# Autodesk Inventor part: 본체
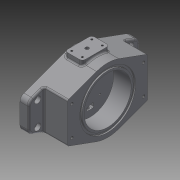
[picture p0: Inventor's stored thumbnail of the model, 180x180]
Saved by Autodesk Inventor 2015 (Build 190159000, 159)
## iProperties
Created: 2023-11
Part Number: 본체
Material: 알루미늄 6061
Document SubType Name: Modeling
Designer: user
Density: 2.7 g/cm^3
Appearance: 기본값
Mass: 1561.22 g
Surface Area: 721.057 cm^2
Volume: 578.228 cm^3
Author: user
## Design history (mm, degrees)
sketch "스케치2"
  geometry: L1 (18.811, 51.683)-(94, 24.317); L2 (94, 24.317)-(94, -24.317); L3 (18.811, -51.683)-(94, -24.317); L4 (0, 0)-(66.664, 0); L5 (0, 55)-(0, -55); L6 (-18.811, 51.683)-(-94, 24.317); L7 (-94, 24.317)-(-94, -24.317); L8 (-18.811, -51.683)-(-94, -24.317); A1 r 55 centre (0, 0) between (18.811, 51.683) and (-18.811, 51.683); A2 r 55 centre (0, 0) between (-18.811, -51.683) and (18.811, -51.683); 1 further point
  constraints: 16 end point, 6 point on circle, 4 symmetric about line, 2 centre point, 2 tangent, 2 vertical, 1 coincident, 1 horizontal, 1 other
  dimensions: "d3" = 94 distance from line of point (0, 0) L2; "d4" = 40 deg angle of L1 L3; "d5" = 55 radius of A1
extrude "돌출1" new body sketch "스케치2" distance "d6" = 15; taper "d7" = 0 deg
sketch "스케치4"
  geometry: L1 (-24.317, 94)-(-51.683, 18.811) reference; L2 (-51.683, -18.811)-(-24.317, -94) reference; L3 (-24.317, -94)-(24.317, -94) reference; L4 (51.683, 18.811)-(24.317, 94) reference; L5 (24.317, 94)-(-24.317, 94) reference; L6 (51.683, -18.811)-(24.317, -94) reference; L7 (-33.78, 68)-(33.78, 68); L8 (-33.78, 68)-(-51.683, 18.811); L9 (33.78, 68)-(51.683, 18.811); L10 (-33.78, -68)-(33.78, -68); L11 (-33.78, -68)-(-51.683, -18.811); L12 (-24.317, -94)-(-51.683, -18.811) reference; L13 (33.78, -68)-(51.683, -18.811); A1 r 55 centre (0, 0) between (-51.683, 18.811) and (-51.683, -18.811) reference; A2 r 55 centre (0, 0) between (51.683, -18.811) and (51.683, 18.811) reference; A3 r 55 centre (0, 0) between (-51.683, 18.811) and (-51.683, -18.811); A4 r 55 centre (0, 0) between (51.683, -18.811) and (51.683, 18.811)
  constraints: 13 end point, 4 point on circle, 4 point on line, 2 centre point, 2 horizontal, 2 parallel, 1 coincident, 1 collinear
  dimensions: "d13" = 68 distance from line of A1.centre L7; "d14" = 68 distance from line of A1.centre L10
extrude "돌출3" join sketch "스케치4" distance "d15" = 40; taper "d16" = 0 deg
sketch "스케치5"
  geometry: C1 r 40 at (0, 0); A1 r 55 centre (0, 0) between (51.683, -18.811) and (51.683, 18.811) reference
  constraints: 1 centre point, 1 coincident
  dimensions: "d17" = 80 diameter of C1
extrude "돌출4" cut sketch "스케치5" distance "d18" = 30; taper "d19" = 0 deg
node "작업 평면1"
sketch "스케치8"
  geometry: L1 (0, 18.811)-(0, -18.811) reference; L2 (10, -23)-(30, -23); L3 (35, -18)-(35, 18); L4 (30, 23)-(10, 23); L5 (5, 18)-(5, -18); L6 (5, -23)-(35, 23); L7 (35, -23)-(5, 23); L8 (0, 18.811)-(0, 94) reference; A1 r 5 centre (10, 18) between (10, 23) and (5, 18); A2 r 5 centre (30, 18) between (35, 18) and (30, 23); A3 r 5 centre (30, -18) between (30, -23) and (35, -18); A4 r 5 centre (10, -18) between (5, -18) and (10, -23); 4 further points
  constraints: 12 end point, 8 point on circle, 8 point on line, 8 tangent, 4 centre point, 4 midpoint, 3 equal radius, 2 parallel, 1 horizontal, 1 horizontal alignment, 1 perpendicular
  dimensions: "d31" = 30 distance of L6.end L7.end; "d32" = 46 distance of L7.end L6.start; "d33" = 20 distance from line of L8 point (20, 0); "d49" = 5 radius of A1
extrude "돌출6" join sketch "스케치8" stored distance "d34" = 20; taper "d35" = 0 deg
sketch "스케치9"
  geometry: C1 r 47.5 at (0, 0); C2 r 43.4 at (0, 0); A1 r 55 centre (0, 0) between (51.683, -18.811) and (51.683, 18.811) reference
  constraints: 2 centre point, 2 coincident
  dimensions: "d36" = 95 diameter of C1; "d37" = 4.1 radial gap between concentric circles of C1 C2
extrude "돌출7" cut sketch "스케치9" distance "d38" = 2.4; taper "d39" = 0 deg
sketch "스케치10"
  geometry: L1 (33.78, 68)-(-33.78, 68) reference; L2 (24.317, -94)-(-24.317, -94) reference; L3 (0, 0)-(0, 111.421); L4 (0, 0)-(71.748, 0); 4 further points
  constraints: 4 end point, 2 horizontal alignment, 2 symmetric about line, 2 vertical alignment, 1 horizontal, 1 vertical
  dimensions: "d40" = 158 distance of point (-20, -79) point (-20, 79); "d41" = 40 distance of point (20, -79) point (-20, -79)
hole "구멍2" sketch "스케치10" at (-20, 79), (20, 79), (-20, -79), (20, -79) diameter "d42" = 6.6; stored, may be unused: countersink angle "d46" = 90 deg, drill point angle "d48" = 0 deg; dims "d43" = 6, "d44" = 11, "d45" = 6.6, "d47" = 8
sketch "스케치11"
  geometry: L1 (0, 0)-(0, 104.924); L2 (0, 0)-(87.032, 0); C1 r 47.5 at (0, 0) reference; 4 further points
  constraints: 4 end point, 2 horizontal alignment, 2 symmetric about line, 2 vertical alignment, 1 horizontal, 1 vertical
  dimensions: "d50" = 50 distance of point (25, 61) point (-25, 61); "d51" = 122 distance of point (-25, -61) point (-25, 61)
hole "구멍3" sketch "스케치11" at (-25, 61), (25, 61), (-25, -61), (25, -61) diameter "d52" = 4.917; stored, may be unused: countersink angle "d56" = 90 deg, drill point angle "d58" = 118 deg; dims "d53" = 12, "d54" = 11, "d55" = 6.6, "d57" = 14
sketch "스케치12"
  geometry: L1 (40, 67.56)-(40, 0) reference; L2 (-15, 9.463)-(-15, 58.096) reference; 3 further points
  constraints: 1 horizontal alignment, 1 midpoint, 1 other
  dimensions: "d59" = 15 distance from line of L1 point (25, 33.78)
feature "엠보싱1" sketch "스케치12" dims "d60" = 0.5, "d61" = 0
sketch "스케치13"
  geometry: L1 (0, 0)-(90.71, 0); L2 (0, 0)-(0, 87.276); C1 r 10 at (0, 0) reference; 2 further points
  constraints: 4 end point, 1 horizontal, 1 symmetric about line, 1 vertical
  dimensions: "d62" = 30 distance of point (15, 17) point (-15, 17); "d63" = 17 distance from line of point (15, 17) L1
hole "구멍4" sketch "스케치13" at (-15, 17), (15, 17) diameter "d64" = 3.242; stored, may be unused: countersink angle "d68" = 90 deg, drill point angle "d70" = 118 deg; dims "d65" = 8, "d66" = 11, "d67" = 6.6, "d69" = 10
fillet "모깎기1" dims "d71" = 10
fillet "모깎기2" dims "d72" = 3
fillet "모깎기3" dims "d73" = 3, "d75" = 0.5
sketch "스케치14"
  geometry: L1 (5, -18)-(5, 18) reference; L2 (5, 0)-(49.755, 0); L3 (10, 23)-(30, 23) reference; L4 (20, 23)-(20, -35.383); 5 further points
  constraints: 4 end point, 2 horizontal alignment, 2 midpoint, 2 symmetric about line, 2 vertical alignment, 1 horizontal, 1 vertical
  dimensions: "d76" = 34 distance of point (29, -17) point (29, 17); "d77" = 18 distance of point (29, 17) point (11, 17)
hole "구멍5" sketch "스케치14" at (11, 17), (29, 17), (11, -17), (29, -17) diameter "d78" = 3.242; stored, may be unused: countersink angle "d82" = 90 deg, drill point angle "d84" = 118 deg; dims "d79" = 8, "d80" = 11, "d81" = 6.6, "d83" = 10
sketch "스케치15"
  geometry: C1 r 17.5 at (0, -9); A1 r 55 centre (0, 0) between (51.683, -18.811) and (51.683, 18.811) reference; A2 r 55 centre (0, 0) between (-51.683, 18.811) and (-51.683, -18.811) reference
  constraints: 1 centre point, 1 vertical alignment
  dimensions: "d85" = 35 diameter of C1; "d86" = 9 distance of C1.centre A2.centre
extrude "돌출8" join sketch "스케치15" distance "d87" = 5; taper "d88" = 0 deg
sketch "스케치16"
  geometry: C1 r 17.5 at (0, 0) reference; 2 further points
  constraints: 1 coincident
hole "구멍6" sketch "스케치16" at (0, 0) diameter "d89" = 16; stored, may be unused: countersink angle "d93" = 90 deg, drill point angle "d95" = 0 deg; dims "d90" = 8, "d91" = 25, "d92" = 8.4, "d94" = 10
sketch "스케치17"
  geometry: C1 r 8 at (0, -9) reference; C2 r 10 at (0, -9)
  constraints: 1 centre point, 1 coincident
  dimensions: "d96" = 20 diameter of C2
extrude "돌출9" cut sketch "스케치17" distance "d97" = 10; taper "d98" = 0 deg
sketch "스케치18"
  geometry: L1 (0, 6)-(18.735, 6); L2 (0, -6)-(23.812, -6); L3 (0, 0)-(83.613, 0); L4 (18.735, 6)-(28.373, 6); L5 (23.812, -6)-(28.373, -6); L6 (28.373, -6)-(35.162, -6); L7 (28.373, 6)-(34.656, 6); C1 r 10 at (0, -9) reference; C2 r 40 at (0, 0) reference; A1 r 24 centre (0, -9) between (23.812, -6) and (18.735, 6); A2 r 29 centre (0, 0) between (28.373, -6) and (28.373, 6)
  constraints: 14 end point, 7 horizontal, 4 point on circle, 2 centre point, 2 coincident, 1 other
  dimensions: "d101" = 12 distance between parallel lines of L2 L1; "d102" = 24 radius of A1; "d103" = 29 radius of A2
extrude "돌출10" cut sketch "스케치18" distance "d104" = 12; taper "d105" = 0 deg
fillet "모깎기4" dims "d106" = 2
fillet "모깎기5" dims "d107" = 2
sketch "스케치19"
  geometry: L1 (0, 18.811)-(0, -18.811) reference; C1 r 3 at (20, 0); 2 further points
  constraints: 1 centre point, 1 horizontal alignment, 1 midpoint
  dimensions: "d108" = 6 diameter of C1; "d109" = 20 distance from line of L1 C1.centre
extrude "돌출11" cut sketch "스케치19" stored distance "d110" = 30; taper "d111" = 0 deg
fillet "모깎기6" dims "d112" = 0.2
chamfer "모따기1" distance "d113" = 0.4; stored, may be unused: second distance "d114" = 2, angle "d115" = 30 deg
chamfer "모따기2" distance "d116" = 1; stored, may be unused: second distance "d117" = 2, angle "d118" = 45 deg
node "솔리드1"
mirror "대칭1"
mirror "대칭2"
mirror "대칭3"
mirror "대칭4"
other parameters: "d30" = 59, "d99" = 48, "d100" = 58
